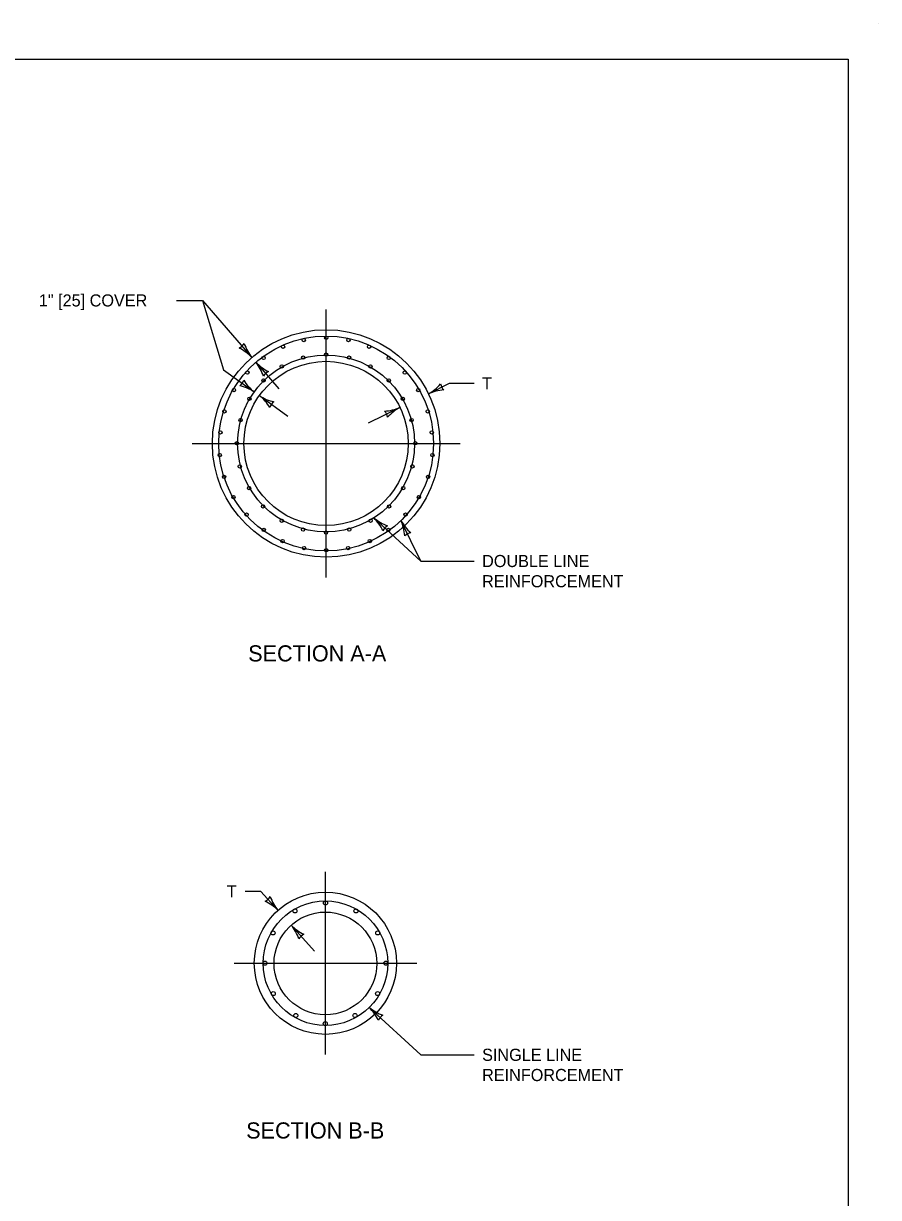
# Model space of a CAD drawing. Extents: x 49991.4 to 50021, y 49987.6 to 50011.4.
# Drawn here: x 50012.67 to 50016.9, y 49993.37 to 49999.18 of the extents above; entities that cross this region are included whole.
import ezdxf

# ---------------------------------------------------------------- set-up
doc = ezdxf.new("R2010")
doc.units = 0
for name, color, linetype in [('Level 1', 7, 'Continuous'), ('Level 2', 7, 'Continuous'), ('Level 3', 7, 'Continuous'), ('Level 5', 7, 'Continuous')]:
    doc.layers.add(name, color=color, linetype=linetype)

msp = doc.modelspace()

# ---------------------------------------------------------------- linework, layer by layer
at = {"layer": 'Level 1'}
for p, q in [((50016.9001, 49999.1756), (50016.9001, 49999.1756)), ((50013.9503, 49997.583), (50013.9503, 49997.583)), ((50014.0561, 49997.6173), (50014.0561, 49997.6173)), ((50014.1666, 49997.6289), (50014.1666, 49997.6289)), ((50014.1666, 49997.6289), (50014.1666, 49997.6289)), ((50014.2771, 49997.6173), (50014.2771, 49997.6173)), ((50014.3829, 49997.583), (50014.3829, 49997.583)), ((50013.8541, 49997.5274), (50013.8541, 49997.5274)), ((50014.0533, 49997.5203), (50014.0533, 49997.5203)), ((50014.1666, 49997.5352), (50014.1666, 49997.5352)), ((50014.1666, 49997.5352), (50014.1666, 49997.5352)), ((50014.2799, 49997.5203), (50014.2799, 49997.5203)), ((50014.4791, 49997.5274), (50014.4791, 49997.5274)), ((50013.9477, 49997.4764), (50013.9477, 49997.4764)), ((50014.3855, 49997.4764), (50014.3855, 49997.4764)), ((50013.7716, 49997.4531), (50013.7716, 49997.4531)), ((50013.8571, 49997.4069), (50013.8571, 49997.4069)), ((50014.4761, 49997.4069), (50014.4761, 49997.4069)), ((50014.5616, 49997.4531), (50014.5616, 49997.4531)), ((50013.7063, 49997.3632), (50013.7063, 49997.3632)), ((50014.6269, 49997.3632), (50014.6269, 49997.3632)), ((50013.7875, 49997.3163), (50013.7875, 49997.3163)), ((50014.5457, 49997.3163), (50014.5457, 49997.3163)), ((50013.6611, 49997.2616), (50013.6611, 49997.2616)), ((50014.6721, 49997.2616), (50014.6721, 49997.2616)), ((50013.7438, 49997.2107), (50013.7438, 49997.2107)), ((50014.5894, 49997.2107), (50014.5894, 49997.2107)), ((50013.6379, 49997.153), (50013.6379, 49997.153)), ((50014.6953, 49997.153), (50014.6953, 49997.153)), ((50013.7288, 49997.0974), (50013.7288, 49997.0974)), ((50014.6044, 49997.0974), (50014.6044, 49997.0974)), ((50013.6379, 49997.0418), (50013.6379, 49997.0418)), ((50014.6953, 49997.0418), (50014.6953, 49997.0418)), ((50013.7437, 49996.9841), (50013.7437, 49996.9841)), ((50014.5895, 49996.9841), (50014.5895, 49996.9841)), ((50013.6611, 49996.9332), (50013.6611, 49996.9332)), ((50014.6721, 49996.9332), (50014.6721, 49996.9332)), ((50013.7063, 49996.8316), (50013.7063, 49996.8316)), ((50013.7875, 49996.8785), (50013.7875, 49996.8785)), ((50014.5457, 49996.8785), (50014.5457, 49996.8785)), ((50014.6269, 49996.8316), (50014.6269, 49996.8316)), ((50013.857, 49996.7879), (50013.857, 49996.7879)), ((50014.4762, 49996.7879), (50014.4762, 49996.7879)), ((50013.9476, 49996.7183), (50013.9476, 49996.7183)), ((50014.3856, 49996.7183), (50014.3856, 49996.7183)), ((50013.8541, 49996.6673), (50013.8541, 49996.6673)), ((50014.0532, 49996.6746), (50014.0532, 49996.6746)), ((50014.1665, 49996.6596), (50014.1665, 49996.6596)), ((50014.1667, 49996.6596), (50014.1667, 49996.6596)), ((50014.28, 49996.6746), (50014.28, 49996.6746)), ((50014.4791, 49996.6673), (50014.4791, 49996.6673)), ((50013.9503, 49996.6118), (50013.9503, 49996.6118)), ((50014.3829, 49996.6118), (50014.3829, 49996.6118)), ((50014.0561, 49996.5775), (50014.0561, 49996.5775)), ((50014.1666, 49996.5658), (50014.1666, 49996.5658)), ((50014.1666, 49996.5658), (50014.1666, 49996.5658)), ((50014.2771, 49996.5775), (50014.2771, 49996.5775)), ((50014.1632, 49994.8085), (50014.1632, 49994.8085)), ((50014.1632, 49994.8085), (50014.1632, 49994.8085))]:
    msp.add_line(p, q, dxfattribs=at)
msp.add_lwpolyline([(49999.3835, 49998.9992), (50016.7501, 49998.9992), (50016.7501, 49987.7988), (49999.3835, 49987.7988)], close=True, dxfattribs=at)
for centre, radius in [((50014.1666, 49997.0974), 0.5628), ((50014.1666, 49997.0974), 0.5315), ((50013.9538, 49997.5764), 0.00819), ((50014.0563, 49997.6092), 0.00819), ((50014.1674, 49997.6208), 0.00819), ((50014.2769, 49997.6092), 0.00819), ((50014.3794, 49997.5764), 0.00819), ((50014.1666, 49997.0974), 0.4377), ((50013.857, 49997.5209), 0.00819), ((50014.0532, 49997.5228), 0.00819), ((50014.1668, 49997.5376), 0.00819), ((50014.2801, 49997.5228), 0.00819), ((50014.4762, 49997.5209), 0.00819), ((50014.1666, 49997.0974), 0.4065), ((50013.9475, 49997.479), 0.00819), ((50014.3857, 49997.479), 0.00819), ((50013.7773, 49997.4483), 0.00819), ((50013.8569, 49997.4094), 0.00819), ((50014.4763, 49997.4094), 0.00819), ((50014.5559, 49997.4483), 0.00819), ((50013.7104, 49997.3615), 0.00819), ((50014.6228, 49997.3615), 0.00819), ((50013.7873, 49997.3188), 0.00819), ((50014.5459, 49997.3188), 0.00819), ((50013.6634, 49997.2562), 0.00819), ((50014.6698, 49997.2562), 0.00819), ((50013.7436, 49997.2132), 0.00819), ((50014.5896, 49997.2132), 0.00819), ((50013.6435, 49997.1523), 0.00819), ((50014.6897, 49997.1523), 0.00819), ((50013.7251, 49997.0985), 0.00819), ((50014.6081, 49997.0985), 0.00819), ((50013.6407, 49997.0399), 0.00819), ((50014.6925, 49997.0399), 0.00819), ((50013.662, 49996.9317), 0.00819), ((50013.7393, 49996.9838), 0.00819), ((50014.5939, 49996.9838), 0.00819), ((50014.6712, 49996.9317), 0.00819), ((50013.7852, 49996.8768), 0.00819), ((50014.548, 49996.8768), 0.00819), ((50013.7076, 49996.8321), 0.00819), ((50014.6256, 49996.8321), 0.00819), ((50013.8547, 49996.7861), 0.00819), ((50014.4785, 49996.7861), 0.00819), ((50013.773, 49996.7453), 0.00819), ((50013.9468, 49996.7151), 0.00819), ((50014.3864, 49996.7151), 0.00819), ((50014.5602, 49996.7453), 0.00819), ((50013.8584, 49996.6698), 0.00819), ((50014.0524, 49996.6714), 0.00819), ((50014.1661, 49996.6565), 0.00819), ((50014.2808, 49996.6714), 0.00819), ((50014.4748, 49996.6698), 0.00819), ((50013.9509, 49996.6143), 0.00819), ((50014.3823, 49996.6143), 0.00819), ((50014.0577, 49996.5802), 0.00819), ((50014.1674, 49996.5688), 0.00819), ((50014.2756, 49996.5802), 0.00819), ((50014.1632, 49994.5257), 0.3518), ((50014.1632, 49994.5257), 0.3081), ((50014.0122, 49994.7846), 0.0102), ((50014.1637, 49994.8236), 0.0102), ((50014.3142, 49994.7846), 0.0102), ((50014.163, 49994.5249), 0.2541), ((50013.9043, 49994.6758), 0.0102), ((50014.4221, 49994.6758), 0.0102), ((50013.8644, 49994.5261), 0.0102), ((50014.4621, 49994.5261), 0.0102), ((50013.9051, 49994.3755), 0.0102), ((50014.4213, 49994.3755), 0.0102), ((50014.017, 49994.2672), 0.0102), ((50014.3094, 49994.2672), 0.0102), ((50014.1623, 49994.2269), 0.0102)]:
    msp.add_circle(centre, radius, dxfattribs=at)
at = {"layer": 'Level 3'}
for p, q in [((50013.4267, 49997.8053), (50013.555, 49997.8053)), ((50013.555, 49997.8053), (50013.659, 49997.4613)), ((50013.555, 49997.8053), (50013.7987, 49997.5233)), ((50013.659, 49997.4613), (50013.8109, 49997.3524)), ((50013.8191, 49997.4996), (50013.9325, 49997.3684)), ((50014.673, 49997.343), (50014.7769, 49997.3952)), ((50014.7769, 49997.3952), (50014.8985, 49997.3952)), ((50013.8362, 49997.3342), (50013.9771, 49997.2332)), ((50014.376, 49997.1997), (50014.5319, 49997.2756)), ((50014.4032, 49996.7291), (50014.6355, 49996.5159)), ((50014.6355, 49996.5159), (50014.537, 49996.7162)), ((50014.6355, 49996.5159), (50014.8985, 49996.5159)), ((50013.8439, 49994.8814), (50013.7668, 49994.8814)), ((50013.8439, 49994.8814), (50013.9283, 49994.7875)), ((50013.9938, 49994.7144), (50014.1096, 49994.5854)), ((50014.3802, 49994.3071), (50014.6355, 49994.0727)), ((50014.6355, 49994.0727), (50014.8985, 49994.0727))]:
    msp.add_line(p, q, dxfattribs=at)
for centre, radius, start, end in [((50013.7148, 49997.6203), 0.0548, 292.96203, 328.68439), ((50013.9727, 49997.6616), 0.2223, 198.27922, 218.46273), ((50013.6301, 49997.3625), 0.233, 43.65052, 62.90037), ((50013.6451, 49997.3613), 0.2223, 18.27923, 38.46273), ((50013.9877, 49997.6604), 0.233, 223.65053, 242.90038), ((50013.7066, 49997.4271), 0.0548, 306.50358, 342.22594), ((50013.9477, 49997.5276), 0.2223, 211.82077, 232.00428), ((50013.903, 49997.4025), 0.0548, 112.96203, 148.68439), ((50013.6846, 49997.1565), 0.233, 57.19207, 76.44192), ((50014.5582, 49997.5458), 0.233, 299.50256, 318.75241), ((50014.7645, 49997.1404), 0.2223, 94.13126, 114.31477), ((50014.7876, 49997.4005), 0.0548, 188.81407, 224.53643), ((50013.6994, 49997.159), 0.2223, 31.82077, 52.00428), ((50013.9625, 49997.53), 0.233, 237.19207, 256.44192), ((50013.9404, 49997.2595), 0.0548, 126.50358, 162.22594), ((50014.4428, 49997.4793), 0.2223, 273.44117, 293.62467), ((50014.4166, 49997.2195), 0.0548, 8.12397, 43.84634), ((50014.6442, 49997.0715), 0.233, 118.81247, 138.06232), ((50014.2462, 49996.5717), 0.2223, 24.91096, 45.09447), ((50014.5521, 49996.9083), 0.233, 230.28226, 249.53211), ((50014.3336, 49996.6264), 0.2223, 3.64223, 23.82574), ((50014.7408, 49996.8292), 0.233, 209.01353, 228.26338), ((50014.4976, 49996.6424), 0.0548, 119.59377, 155.31613), ((50014.5936, 49996.6012), 0.0548, 98.32504, 134.0474), ((50013.8426, 49994.8829), 0.0548, 294.04529, 329.76765), ((50014.0997, 49994.9291), 0.2223, 199.36248, 219.54599), ((50013.7627, 49994.6235), 0.233, 44.73378, 63.98363), ((50013.8224, 49994.5729), 0.2223, 19.36248, 39.54599), ((50014.1593, 49994.8784), 0.233, 224.73378, 243.98363), ((50014.0795, 49994.619), 0.0548, 114.04529, 149.76765), ((50014.2233, 49994.1496), 0.2223, 24.90887, 45.09238), ((50014.5291, 49994.4863), 0.233, 230.28017, 249.53002), ((50014.4747, 49994.2204), 0.0548, 119.59168, 155.31404)]:
    msp.add_arc(centre, radius, start, end, dxfattribs=at)
at = {"layer": 'Level 5'}
for p, q in [((50014.1666, 49996.4345), (50014.1666, 49997.7602)), ((50013.5037, 49997.0974), (50014.8294, 49997.0974)), ((50014.1632, 49994.0739), (50014.1632, 49994.9774)), ((50013.7114, 49994.5257), (50014.6149, 49994.5257))]:
    msp.add_line(p, q, dxfattribs=at)

# ---------------------------------------------------------------- texts
at = {"layer": 'Level 2'}
for s, height, p in [('1" [25] COVER', 0.06, (50012.7451, 49997.7753)), ('T', 0.06, (50014.9385, 49997.3652)), ('DOUBLE LINE', 0.06, (50014.9385, 49996.4859)), ('REINFORCEMENT', 0.06, (50014.9385, 49996.3859)), ('SECTION A-A', 0.08, (50013.781, 49996.0188)), ('T', 0.06, (50013.6748, 49994.8514)), ('SINGLE LINE ', 0.06, (50014.9385, 49994.0427)), ('REINFORCEMENT', 0.06, (50014.9385, 49993.9427)), ('SECTION B-B', 0.08, (50013.7711, 49993.6583))]:
    msp.add_text(s, height=height, dxfattribs=at).set_placement(p)

doc.saveas('drawing.dxf')
